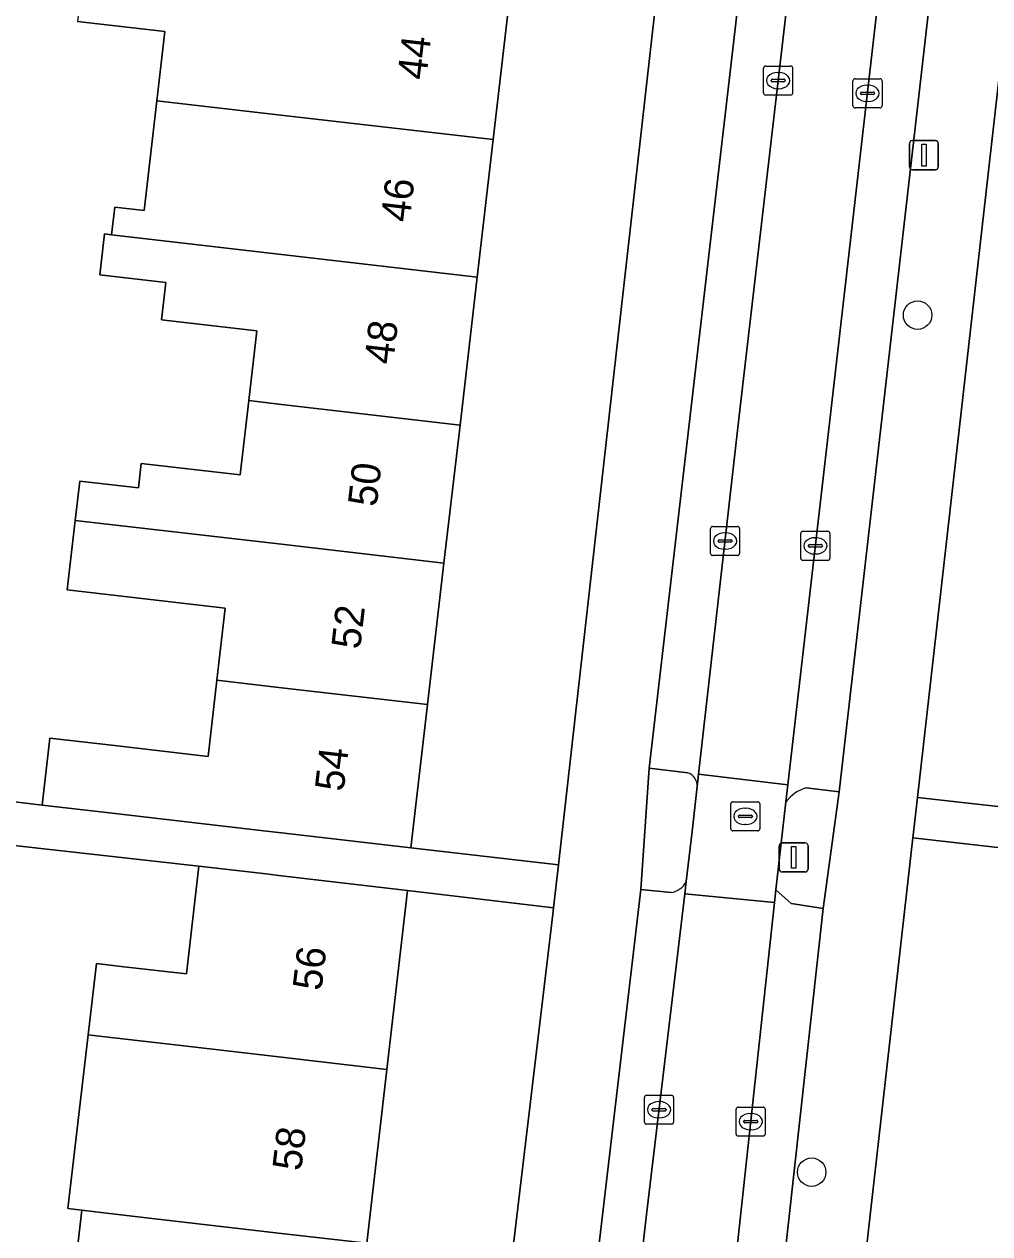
# Model space of a CAD drawing. Extents: x 161692 to 162379, y 380760 to 381678.
# Drawn here: x 161991.17 to 162024.33, y 381028.56 to 381070.14 of the extents above; entities that cross this region are included whole.
import ezdxf

# ---------------------------------------------------------------- set-up
doc = ezdxf.new("R2010")
doc.units = 0
for name, color, linetype in [('IMGEO_Boom', 7, 'Continuous'), ('IMGEO_Erf', 7, 'Continuous'), ('IMGEO_Kolk', 7, 'Continuous'), ('IMGEO_Lichtmast', 7, 'Continuous'), ('IMGEO_Pand', 7, 'Continuous'), ('IMGEO_Pand_nummerreeks', 7, 'Continuous'), ('IMGEO_Parkeervlak_open', 7, 'Continuous'), ('IMGEO_Rijbaan_lokaal_open', 7, 'Continuous'), ('IMGEO_Rioolput', 7, 'Continuous'), ('IMGEO_Voetpad_open', 7, 'Continuous')]:
    doc.layers.add(name, color=color, linetype=linetype)

msp = doc.modelspace()

# ---------------------------------------------------------------- linework, layer by layer
at = {"layer": 'IMGEO_Boom'}
for centre in [(162021.851, 381060.137), (162018.213, 381030.683)]:
    msp.add_circle(centre, 0.489, dxfattribs=at)
at = {"layer": 'IMGEO_Erf'}
for points in [[(162015.033, 381090.181), (162010.119, 381090.735), (162009.531, 381085.664), (162008.985, 381080.948), (162008.409, 381075.981), (162007.857, 381071.218), (162007.271, 381066.168), (162006.724, 381061.442), (162006.134, 381056.359), (162005.584, 381051.613), (162005.021, 381046.75), (162004.45, 381041.827), (162009.512, 381041.24)], [(162029.902, 381069.631), (162030.396, 381073.978), (162030.902, 381078.436), (162031.4, 381082.824), (162031.897, 381087.196), (162026.889, 381087.778), (162025.499, 381075.815), (162021.85, 381043.562), (162026.876, 381042.993), (162027.389, 381047.51), (162027.905, 381052.055), (162028.399, 381056.401), (162028.887, 381060.699), (162029.403, 381065.244)], [(161993.148, 381029.374), (161992.669, 381029.43), (161993.361, 381035.406), (161993.645, 381037.854), (161994.123, 381037.799), (161994.586, 381037.745), (161996.736, 381037.497), (161997.165, 381041.197), (161982.721, 381042.814), (161981.398, 381031.731), (161981.809, 381031.681), (161981.76, 381031.265), (161981.692, 381030.702), (161981.47, 381028.823), (161981.406, 381028.279), (161980.964, 381028.339), (161978.51, 381007.398), (161989.335, 381006.129), (161990.006, 381011.923), (161991.809, 381011.714), (161992.484, 381017.54), (161991.786, 381017.621), (161992.461, 381023.448)], [(162024.547, 381023.408), (162025.25, 381029.573), (162025.936, 381035.586), (162026.624, 381041.617), (162021.693, 381042.175), (162018.038, 381009.86), (162016.694, 381000), (162015.99, 380993.672), (162021.098, 380993.178), (162021.786, 380999.214), (162021.876, 381000), (162022.484, 381005.331), (162023.169, 381011.335), (162023.855, 381017.349)], [(162009.322, 381039.552), (162009.346, 381039.768), (162004.334, 381040.366), (162003.621, 381034.216), (162002.928, 381028.24), (162002.241, 381022.314), (162001.566, 381016.488), (162000.891, 381010.661), (162000.219, 381004.867), (162005.116, 381004.283)]]:
    msp.add_lwpolyline(points, close=True, dxfattribs=at)
msp.add_lwpolyline([(161986.174, 381043.974), (161991.781, 381043.296), (161992.049, 381045.6), (161994.264, 381045.343), (161997.48, 381044.97), (161997.784, 381047.589), (161998.07, 381050.061), (161992.639, 381050.691), (161992.916, 381053.082), (161993.073, 381054.433), (161995.089, 381054.199), (161995.186, 381055.038), (161998.58, 381054.645), (161998.876, 381057.2), (161999.154, 381059.601), (161995.884, 381059.979), (161996.032, 381061.257), (161993.761, 381061.52), (161993.924, 381062.926), (161994.163, 381062.898), (161994.273, 381063.848), (161995.283, 381063.731), (161995.72, 381067.506), (161995.995, 381069.879), (161992.992, 381070.227)], dxfattribs=at)
at = {"layer": 'IMGEO_Kolk'}
for p, q in [((162016.634, 381068.699), (162017.486, 381068.699)), ((162016.559, 381067.773), (162016.559, 381068.625)), ((162017.047, 381068.479), (162017.072, 381068.479)), ((162017.56, 381068.625), (162017.56, 381067.773)), ((162019.703, 381068.26), (162020.555, 381068.26)), ((162016.818, 381068.193), (162016.818, 381068.205)), ((162017.256, 381068.156), (162016.858, 381068.156)), ((162016.861, 381068.242), (162017.259, 381068.242)), ((162017.07, 381067.919), (162017.045, 381067.919)), ((162017.302, 381068.205), (162017.302, 381068.193)), ((162019.628, 381067.334), (162019.628, 381068.186)), ((162020.116, 381068.04), (162020.141, 381068.04)), ((162020.629, 381068.186), (162020.629, 381067.334)), ((162017.486, 381067.699), (162016.634, 381067.699)), ((162019.887, 381067.754), (162019.887, 381067.766)), ((162020.325, 381067.717), (162019.927, 381067.717)), ((162019.93, 381067.803), (162020.328, 381067.803)), ((162020.139, 381067.48), (162020.114, 381067.48)), ((162020.371, 381067.766), (162020.371, 381067.754)), ((162020.555, 381067.26), (162019.703, 381067.26)), ((162014.812, 381052.874), (162015.664, 381052.874)), ((162014.737, 381051.948), (162014.737, 381052.8)), ((162015.225, 381052.654), (162015.25, 381052.654)), ((162015.738, 381052.8), (162015.738, 381051.948)), ((162017.839, 381051.782), (162017.839, 381052.634)), ((162017.914, 381052.708), (162018.766, 381052.708)), ((162018.327, 381052.488), (162018.352, 381052.488)), ((162018.84, 381052.634), (162018.84, 381051.782)), ((162014.996, 381052.368), (162014.996, 381052.38)), ((162015.434, 381052.331), (162015.036, 381052.331)), ((162015.039, 381052.417), (162015.437, 381052.417)), ((162015.248, 381052.094), (162015.223, 381052.094)), ((162015.48, 381052.38), (162015.48, 381052.368)), ((162018.098, 381052.202), (162018.098, 381052.214)), ((162018.536, 381052.165), (162018.138, 381052.165)), ((162018.141, 381052.251), (162018.539, 381052.251)), ((162018.582, 381052.214), (162018.582, 381052.202)), ((162015.664, 381051.874), (162014.812, 381051.874)), ((162018.766, 381051.708), (162017.914, 381051.708)), ((162018.35, 381051.928), (162018.325, 381051.928)), ((162012.544, 381033.328), (162013.396, 381033.328)), ((162012.469, 381032.402), (162012.469, 381033.254)), ((162012.957, 381033.108), (162012.982, 381033.108)), ((162013.47, 381033.254), (162013.47, 381032.402)), ((162015.693, 381032.92), (162016.545, 381032.92)), ((162012.728, 381032.822), (162012.728, 381032.834)), ((162013.166, 381032.785), (162012.768, 381032.785)), ((162012.771, 381032.871), (162013.169, 381032.871)), ((162012.98, 381032.548), (162012.955, 381032.548)), ((162013.212, 381032.834), (162013.212, 381032.822)), ((162015.618, 381031.994), (162015.618, 381032.846)), ((162016.106, 381032.7), (162016.131, 381032.7)), ((162016.619, 381032.846), (162016.619, 381031.994)), ((162013.396, 381032.328), (162012.544, 381032.328)), ((162015.877, 381032.414), (162015.877, 381032.426)), ((162016.315, 381032.377), (162015.917, 381032.377)), ((162015.92, 381032.463), (162016.318, 381032.463)), ((162016.129, 381032.14), (162016.104, 381032.14)), ((162016.361, 381032.426), (162016.361, 381032.414)), ((162016.545, 381031.92), (162015.693, 381031.92))]:
    msp.add_line(p, q, dxfattribs=at)
for points in [[(162016.634, 381068.699), (162017.486, 381068.699)], [(162016.559, 381067.773), (162016.559, 381068.625)], [(162017.56, 381068.625), (162017.56, 381067.773)], [(162019.703, 381068.26), (162020.555, 381068.26)], [(162019.628, 381067.334), (162019.628, 381068.186)], [(162020.629, 381068.186), (162020.629, 381067.334)], [(162017.486, 381067.699), (162016.634, 381067.699)], [(162020.555, 381067.26), (162019.703, 381067.26)], [(162014.812, 381052.874), (162015.664, 381052.874)], [(162014.737, 381051.948), (162014.737, 381052.8)], [(162015.738, 381052.8), (162015.738, 381051.948)], [(162017.839, 381051.782), (162017.839, 381052.634)], [(162017.914, 381052.708), (162018.766, 381052.708)], [(162018.84, 381052.634), (162018.84, 381051.782)], [(162015.664, 381051.874), (162014.812, 381051.874)], [(162018.766, 381051.708), (162017.914, 381051.708)], [(162012.544, 381033.328), (162013.396, 381033.328)], [(162012.469, 381032.402), (162012.469, 381033.254)], [(162013.47, 381033.254), (162013.47, 381032.402)], [(162015.693, 381032.92), (162016.545, 381032.92)], [(162015.618, 381031.994), (162015.618, 381032.846)], [(162016.619, 381032.846), (162016.619, 381031.994)], [(162013.396, 381032.328), (162012.544, 381032.328)], [(162016.545, 381031.92), (162015.693, 381031.92)]]:
    msp.add_lwpolyline(points, dxfattribs=at)
for centre, radius, start, end in [((162016.636, 381068.623), 0.0765, 91.552, 178.448), ((162016.636, 381068.623), 0.0765, 91.552, 178.448), ((162017.484, 381068.623), 0.0765, 1.552, 88.448), ((162017.484, 381068.623), 0.0765, 1.552, 88.448), ((162019.705, 381068.184), 0.0765, 91.552, 178.448), ((162019.705, 381068.184), 0.0765, 91.552, 178.448), ((162020.553, 381068.184), 0.0765, 1.552, 88.448), ((162020.553, 381068.184), 0.0765, 1.552, 88.448), ((162016.858, 381068.202), 0.0403, 85.8775, 175.7526), ((162016.855, 381068.192), 0.0366, 178.938, 274.7102), ((162017.259, 381068.199), 0.043, 264.8664, 352.4533), ((162017.263, 381068.204), 0.0386, 1.7309, 96.639), ((162016.636, 381067.775), 0.0765, 181.552, 268.448), ((162016.636, 381067.775), 0.0765, 181.552, 268.448), ((162017.484, 381067.775), 0.0765, 271.552, 358.448), ((162017.484, 381067.775), 0.0765, 271.552, 358.448), ((162019.927, 381067.763), 0.0403, 85.8775, 175.7526), ((162019.924, 381067.753), 0.0366, 178.938, 274.7102), ((162020.328, 381067.76), 0.043, 264.8664, 352.4533), ((162020.332, 381067.765), 0.0386, 1.7309, 96.639), ((162019.705, 381067.336), 0.0765, 181.552, 268.448), ((162019.705, 381067.336), 0.0765, 181.552, 268.448), ((162020.553, 381067.336), 0.0765, 271.552, 358.448), ((162020.553, 381067.336), 0.0765, 271.552, 358.448), ((162014.814, 381052.798), 0.0765, 91.552, 178.448), ((162014.814, 381052.798), 0.0765, 91.552, 178.448), ((162015.662, 381052.798), 0.0765, 1.552, 88.448), ((162015.662, 381052.798), 0.0765, 1.552, 88.448), ((162017.916, 381052.632), 0.0765, 91.552, 178.448), ((162017.916, 381052.632), 0.0765, 91.552, 178.448), ((162018.764, 381052.632), 0.0765, 1.552, 88.448), ((162018.764, 381052.632), 0.0765, 1.552, 88.448), ((162015.036, 381052.377), 0.0403, 85.8775, 175.7526), ((162015.033, 381052.367), 0.0366, 178.938, 274.7102), ((162015.437, 381052.374), 0.043, 264.8664, 352.4533), ((162015.441, 381052.379), 0.0386, 1.7309, 96.639), ((162018.138, 381052.211), 0.0403, 85.8775, 175.7526), ((162018.135, 381052.201), 0.0366, 178.938, 274.7102), ((162018.539, 381052.208), 0.043, 264.8664, 352.4533), ((162018.543, 381052.213), 0.0386, 1.7309, 96.639), ((162014.814, 381051.95), 0.0765, 181.552, 268.448), ((162014.814, 381051.95), 0.0765, 181.552, 268.448), ((162015.662, 381051.95), 0.0765, 271.552, 358.448), ((162015.662, 381051.95), 0.0765, 271.552, 358.448), ((162017.916, 381051.784), 0.0765, 181.552, 268.448), ((162017.916, 381051.784), 0.0765, 181.552, 268.448), ((162018.764, 381051.784), 0.0765, 271.552, 358.448), ((162018.764, 381051.784), 0.0765, 271.552, 358.448), ((162012.546, 381033.252), 0.0765, 91.552, 178.448), ((162012.546, 381033.252), 0.0765, 91.552, 178.448), ((162013.394, 381033.252), 0.0765, 1.552, 88.448), ((162013.394, 381033.252), 0.0765, 1.552, 88.448), ((162015.695, 381032.844), 0.0765, 91.552, 178.448), ((162015.695, 381032.844), 0.0765, 91.552, 178.448), ((162016.543, 381032.844), 0.0765, 1.552, 88.448), ((162016.543, 381032.844), 0.0765, 1.552, 88.448), ((162012.768, 381032.831), 0.0403, 85.8775, 175.7526), ((162012.765, 381032.821), 0.0366, 178.938, 274.7102), ((162013.169, 381032.828), 0.043, 264.8664, 352.4533), ((162013.173, 381032.833), 0.0386, 1.7309, 96.639), ((162012.546, 381032.404), 0.0765, 181.552, 268.448), ((162012.546, 381032.404), 0.0765, 181.552, 268.448), ((162013.394, 381032.404), 0.0765, 271.552, 358.448), ((162013.394, 381032.404), 0.0765, 271.552, 358.448), ((162015.917, 381032.423), 0.0403, 85.8775, 175.7526), ((162015.914, 381032.413), 0.0366, 178.938, 274.7102), ((162016.318, 381032.42), 0.043, 264.8664, 352.4533), ((162016.322, 381032.425), 0.0386, 1.7309, 96.639), ((162015.695, 381031.996), 0.0765, 181.552, 268.448), ((162015.695, 381031.996), 0.0765, 181.552, 268.448), ((162016.543, 381031.996), 0.0765, 271.552, 358.448), ((162016.543, 381031.996), 0.0765, 271.552, 358.448)]:
    msp.add_arc(centre, radius, start, end, dxfattribs=at)
for centre, major_axis, ratio, start_param, end_param in [((162017.046, 381068.199), (-0.387, 0.002), 0.722429, 4.712389, 7.853982), ((162017.071, 381068.199), (-0.39, 0.002), 0.717154, 1.570796, 4.712389), ((162020.115, 381067.76), (-0.387, 0.002), 0.722429, 4.712389, 7.853982), ((162020.14, 381067.76), (-0.39, 0.002), 0.717154, 1.570796, 4.712389), ((162015.224, 381052.374), (-0.387, 0.002), 0.722429, 4.712389, 7.853982), ((162015.249, 381052.374), (-0.39, 0.002), 0.717154, 1.570796, 4.712389), ((162018.326, 381052.208), (-0.387, 0.002), 0.722429, 4.712389, 7.853982), ((162018.351, 381052.208), (-0.39, 0.002), 0.717154, 1.570796, 4.712389), ((162012.956, 381032.828), (-0.387, 0.002), 0.722429, 4.712389, 7.853982), ((162012.981, 381032.828), (-0.39, 0.002), 0.717154, 1.570796, 4.712389), ((162016.105, 381032.42), (-0.387, 0.002), 0.722429, 4.712389, 7.853982), ((162016.13, 381032.42), (-0.39, 0.002), 0.717154, 1.570796, 4.712389)]:
    msp.add_ellipse(centre, major_axis=major_axis, ratio=ratio, start_param=start_param, end_param=end_param, dxfattribs=at)
at = {"layer": 'IMGEO_Lichtmast'}
for p, q in [((162021.571, 381065.235), (162021.571, 381066.035)), ((162021.571, 381066.035), (162021.571, 381065.235)), ((162021.671, 381066.135), (162022.461, 381066.135)), ((162022.461, 381066.135), (162021.671, 381066.135)), ((162022.561, 381066.035), (162022.561, 381065.235)), ((162022.561, 381065.235), (162022.561, 381066.035)), ((162022.461, 381065.135), (162021.671, 381065.135)), ((162021.671, 381065.135), (162022.461, 381065.135)), ((162017.101, 381041.101), (162017.101, 381041.901)), ((162017.101, 381041.901), (162017.101, 381041.101)), ((162017.201, 381042.001), (162017.991, 381042.001)), ((162017.991, 381042.001), (162017.201, 381042.001)), ((162018.091, 381041.901), (162018.091, 381041.101)), ((162018.091, 381041.101), (162018.091, 381041.901)), ((162017.991, 381041.001), (162017.201, 381041.001)), ((162017.201, 381041.001), (162017.991, 381041.001))]:
    msp.add_line(p, q, dxfattribs=at)
for points in [[(162021.991, 381066.01), (162022.141, 381066.01), (162022.141, 381065.26), (162021.991, 381065.26), (162021.991, 381066.01)], [(162017.521, 381041.876), (162017.671, 381041.876), (162017.671, 381041.126), (162017.521, 381041.126), (162017.521, 381041.876)]]:
    msp.add_lwpolyline(points, dxfattribs=at)
for centre, start, end in [((162021.671, 381066.035), 90, 180), ((162021.671, 381066.035), 90, 180), ((162022.461, 381066.035), 0, 90), ((162022.461, 381066.035), 360, 90), ((162021.671, 381065.235), 180, 270), ((162021.671, 381065.235), 180, 270), ((162022.461, 381065.235), 270, 0), ((162022.461, 381065.235), 270, 0), ((162017.201, 381041.901), 90, 180), ((162017.201, 381041.901), 90, 180), ((162017.991, 381041.901), 0, 90), ((162017.991, 381041.901), 360, 90), ((162017.201, 381041.101), 180, 270), ((162017.201, 381041.101), 180, 270), ((162017.991, 381041.101), 270, 0), ((162017.991, 381041.101), 270, 0)]:
    msp.add_arc(centre, 0.1, start, end, dxfattribs=at)
at = {"layer": 'IMGEO_Pand'}
for points in [[(162007.857, 381071.218), (162000, 381072.129), (161995.166, 381072.69), (161993.302, 381072.906), (161992.992, 381070.227), (161995.995, 381069.879), (161995.72, 381067.506), (161999.975, 381067.013), (162007.271, 381066.168)], [(162007.271, 381066.168), (161999.975, 381067.013), (161995.72, 381067.506), (161995.283, 381063.731), (161994.273, 381063.848), (161994.163, 381062.898), (162000, 381062.221), (162006.724, 381061.442)], [(162006.724, 381061.442), (162000, 381062.221), (161994.163, 381062.898), (161993.924, 381062.926), (161993.761, 381061.52), (161996.032, 381061.257), (161995.884, 381059.979), (161999.154, 381059.601), (161998.876, 381057.2), (162000, 381057.07), (162006.134, 381056.359)], [(161992.916, 381053.082), (162000, 381052.261), (162005.584, 381051.613), (162006.134, 381056.359), (162000, 381057.07), (161998.876, 381057.2), (161998.58, 381054.645), (161995.186, 381055.038), (161995.089, 381054.199), (161993.073, 381054.433)], [(162005.021, 381046.75), (162005.584, 381051.613), (162000, 381052.261), (161992.916, 381053.082), (161992.639, 381050.691), (161998.07, 381050.061), (161997.784, 381047.589), (162000, 381047.332)], [(162005.021, 381046.75), (162000, 381047.332), (161997.784, 381047.589), (161997.48, 381044.97), (161994.264, 381045.343), (161992.049, 381045.6), (161991.781, 381043.296), (161993.997, 381043.039), (161999.484, 381042.404), (162000.001, 381042.343), (162004.45, 381041.827)], [(161993.361, 381035.406), (161993.84, 381035.35), (161996.452, 381035.047), (162000, 381034.636), (162003.621, 381034.216), (162004.334, 381040.366), (162000, 381040.869), (161999.368, 381040.943), (161997.165, 381041.197), (161996.736, 381037.497), (161994.586, 381037.745), (161994.123, 381037.799), (161993.645, 381037.854)], [(162003.621, 381034.216), (162000, 381034.636), (161996.452, 381035.047), (161993.84, 381035.35), (161993.361, 381035.406), (161992.669, 381029.43), (161993.148, 381029.374), (161993.897, 381029.287), (161995.759, 381029.071), (162000, 381028.58), (162002.928, 381028.24)], [(162002.928, 381028.24), (162000, 381028.58), (161995.759, 381029.071), (161993.897, 381029.287), (161993.148, 381029.374), (161992.461, 381023.448), (161995.072, 381023.145), (162000, 381022.574), (162002.241, 381022.314)]]:
    msp.add_lwpolyline(points, close=True, dxfattribs=at)
at = {"layer": 'IMGEO_Parkeervlak_open'}
for points in [[(162018.82, 381087.735), (162017.652, 381087.808), (162012.631, 381044.57), (162013.964, 381044.409)], [(162014.282, 381043.933), (162014.331, 381044.365), (162015.725, 381056.673), (162017.736, 381074.025), (162019.283, 381087.682), (162019.333, 381088.124)], [(162022.506, 381087.765), (162022.452, 381087.318), (162020.88, 381074.29), (162018.867, 381056.828), (162017.398, 381043.995), (162017.331, 381043.409)], [(162018.028, 381043.889), (162019.158, 381043.753), (162024.115, 381087.105), (162023.01, 381087.254)], [(162013.964, 381044.409), (162012.631, 381044.57), (162012.34, 381040.393), (162013.382, 381040.294)], [(162013.902, 381040.668), (162014.107, 381042.391), (162014.282, 381043.933)], [(162017.331, 381043.409), (162016.985, 381040.382), (162017.508, 381039.914), (162018.613, 381039.74), (162019.158, 381043.753), (162018.028, 381043.889)], [(162013.382, 381040.294), (162012.34, 381040.393), (162008.268, 381005.751), (162009.259, 381005.577)], [(162009.735, 381005.057), (162010.698, 381013.15), (162012.542, 381029.228), (162013.852, 381040.249), (162013.902, 381040.668)], [(162012.38, 380994.993), (162013.574, 380994.888), (162014.223, 381000), (162018.613, 381039.74), (162017.508, 381039.914), (162016.985, 381040.382), (162016.939, 381039.955), (162015.661, 381028.223), (162013.811, 381012.386), (162012.264, 381000), (162011.644, 380994.671)]]:
    msp.add_lwpolyline(points, dxfattribs=at)
for centre, radius, start, end in [((162013.802, 381043.957), 0.48, 357.1758, 70.3154), ((162013.802, 381043.957), 0.48, 357.1758, 70.3154), ((162018.369, 381042.648), 1.287, 105.3557, 143.752), ((162018.369, 381042.648), 1.287, 105.3557, 143.752), ((162013.303, 381040.953), 0.663, 276.8612, 334.5885), ((162013.303, 381040.953), 0.663, 276.8612, 334.5885)]:
    msp.add_arc(centre, radius, start, end, dxfattribs=at)
at = {"layer": 'IMGEO_Rijbaan_lokaal_open'}
for points in [[(162017.398, 381043.995), (162018.867, 381056.828), (162020.88, 381074.29), (162022.452, 381087.318), (162019.283, 381087.682), (162017.736, 381074.025), (162015.725, 381056.673), (162014.331, 381044.365)], [(162014.107, 381042.391), (162013.902, 381040.668), (162013.852, 381040.249), (162016.939, 381039.955), (162016.985, 381040.382), (162017.331, 381043.409), (162017.398, 381043.995), (162014.331, 381044.365), (162014.282, 381043.933)], [(162011.344, 380992.103), (162011.644, 380994.671), (162012.264, 381000), (162013.811, 381012.386), (162015.661, 381028.223), (162016.939, 381039.955), (162013.852, 381040.249), (162012.542, 381029.228), (162010.698, 381013.15), (162009.735, 381005.057), (162009.423, 381002.428), (162009.134, 381000), (162008.854, 380997.766), (162008.814, 380997.445), (162008.477, 380994.755), (162005.298, 380968.939), (162008.606, 380968.584), (162008.704, 380969.423), (162010.162, 380981.956), (162010.301, 380983.14)]]:
    msp.add_lwpolyline(points, close=True, dxfattribs=at)
at = {"layer": 'IMGEO_Rioolput'}
for p, q in [((162015.435, 381042.485), (162015.435, 381043.337)), ((162015.51, 381043.411), (162016.362, 381043.411)), ((162016.436, 381043.337), (162016.436, 381042.485)), ((162015.694, 381042.905), (162015.694, 381042.917)), ((162015.737, 381042.954), (162016.135, 381042.954)), ((162015.923, 381043.191), (162015.948, 381043.191)), ((162016.178, 381042.917), (162016.178, 381042.905)), ((162016.132, 381042.868), (162015.734, 381042.868)), ((162015.946, 381042.631), (162015.921, 381042.631)), ((162016.362, 381042.411), (162015.51, 381042.411))]:
    msp.add_line(p, q, dxfattribs=at)
for points in [[(162015.435, 381042.485), (162015.435, 381043.337)], [(162015.51, 381043.411), (162016.362, 381043.411)], [(162016.436, 381043.337), (162016.436, 381042.485)], [(162016.362, 381042.411), (162015.51, 381042.411)]]:
    msp.add_lwpolyline(points, dxfattribs=at)
for centre, radius, start, end in [((162015.512, 381043.335), 0.0765, 91.552, 178.448), ((162015.512, 381043.335), 0.0765, 91.552, 178.448), ((162016.36, 381043.335), 0.0765, 1.552, 88.448), ((162016.36, 381043.335), 0.0765, 1.552, 88.448), ((162015.734, 381042.914), 0.0403, 85.8775, 175.7526), ((162015.731, 381042.904), 0.0366, 178.938, 274.7102), ((162016.135, 381042.911), 0.043, 264.8664, 352.4533), ((162016.139, 381042.916), 0.0386, 1.7309, 96.639), ((162015.512, 381042.487), 0.0765, 181.552, 268.448), ((162015.512, 381042.487), 0.0765, 181.552, 268.448), ((162016.36, 381042.487), 0.0765, 271.552, 358.448), ((162016.36, 381042.487), 0.0765, 271.552, 358.448)]:
    msp.add_arc(centre, radius, start, end, dxfattribs=at)
for centre, major_axis, ratio, start_param, end_param in [((162015.922, 381042.911), (-0.387, 0.002), 0.722429, 4.712389, 7.853982), ((162015.947, 381042.911), (-0.39, 0.002), 0.717154, 1.570796, 4.712389)]:
    msp.add_ellipse(centre, major_axis=major_axis, ratio=ratio, start_param=start_param, end_param=end_param, dxfattribs=at)
at = {"layer": 'IMGEO_Voetpad_open'}
for points in [[(162026.345, 381148.219), (162026.366, 381148.384), (162026.485, 381149.36), (162021.813, 381150.411), (162020.89, 381142.109), (162015.25, 381092.109), (162015.033, 381090.181), (162009.512, 381041.24), (162009.346, 381039.768), (162009.322, 381039.552), (162005.116, 381004.283), (162004.93, 381002.725), (162004.605, 381000), (162001.24, 380971.782), (162003.756, 380969.496), (162007.002, 380997.196), (162008.247, 380997.073)], [(162009.259, 381005.577), (162008.268, 381005.751), (162012.34, 381040.393), (162012.631, 381044.57), (162017.652, 381087.808)], [(162023.01, 381087.254), (162024.115, 381087.105), (162019.158, 381043.753), (162018.613, 381039.74), (162014.223, 381000), (162013.574, 380994.888), (162012.38, 380994.993)], [(162013.002, 380966.811), (162015.772, 380991.71), (162015.965, 380993.447), (162015.99, 380993.672), (162016.694, 381000), (162018.038, 381009.86), (162021.693, 381042.175), (162021.85, 381043.562), (162025.499, 381075.815)], [(162049.418, 381048.642), (162049.011, 381045.054), (162048.478, 381040.494), (162048.259, 381040.52), (162048.247, 381040.412), (162040.053, 381041.343), (162040.068, 381041.477), (162034.441, 381042.134), (162031.861, 381042.427), (162026.876, 381042.993), (162021.85, 381043.562), (162021.693, 381042.175), (162026.624, 381041.617), (162031.593, 381041.053), (162034.756, 381040.694), (162048.043, 381039.141), (162047.737, 381036.523), (162047.331, 381033.146), (162046.87, 381029.31), (162046.275, 381024.354)], [(161982.721, 381042.814), (161997.165, 381041.197), (161999.368, 381040.943), (162000, 381040.869), (162004.334, 381040.366), (162009.346, 381039.768), (162009.512, 381041.24), (162004.45, 381041.827), (162000.001, 381042.343), (161999.484, 381042.404), (161993.997, 381043.039), (161991.781, 381043.296), (161986.174, 381043.974)]]:
    msp.add_lwpolyline(points, dxfattribs=at)

# ---------------------------------------------------------------- texts
at = {"layer": 'IMGEO_Pand_nummerreeks'}
for s, rotation, p in [('44', 83.3883, (162004.969, 381068.195)), ('46', 83.3883, (162004.402, 381063.305)), ('48', 83.3883, (162003.836, 381058.417)), ('50', 83.3883, (162003.27, 381053.526)), ('52', 83.3883, (162002.702, 381048.629)), ('54', 83.3883, (162002.135, 381043.741)), ('56', 83.033, (162001.371, 381036.895)), ('58', 83.3825, (162000.678, 381030.701))]:
    msp.add_text(s, height=1, rotation=rotation, dxfattribs=at).set_placement(p)

doc.saveas('drawing.dxf')
